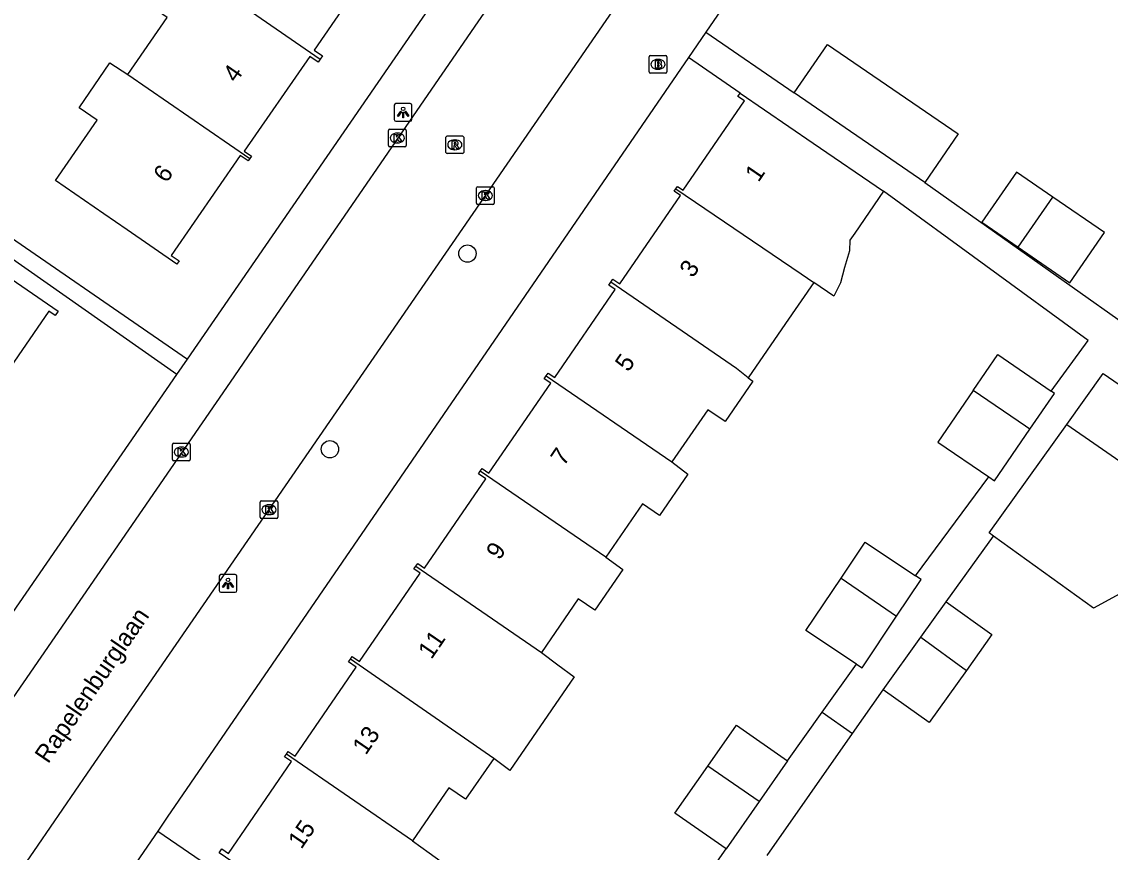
# Model space of a CAD drawing. Extents: x 160158 to 160921, y 381517 to 382041.
# Drawn here: x 160666.6 to 160728, y 381762 to 381808.9 of the extents above; entities that cross this region are included whole.
import ezdxf

# ---------------------------------------------------------------- set-up
doc = ezdxf.new("R2010")
doc.units = 0
for name, color, linetype in [('IMGEO_Boom', 7, 'Continuous'), ('IMGEO_Brandkraan', 7, 'Continuous'), ('IMGEO_Kolk', 7, 'Continuous'), ('IMGEO_Lichtpunt', 7, 'Continuous'), ('IMGEO_Openbare_ruimte_label', 7, 'Continuous'), ('IMGEO_Pand', 7, 'Continuous'), ('IMGEO_Pand_nummerreeks', 7, 'Continuous'), ('IMGEO_Rijbaan_lokaal_open', 7, 'Continuous'), ('IMGEO_Rioolput', 7, 'Continuous'), ('IMGEO_Voetpad_halfverhard', 7, 'Continuous'), ('IMGEO_Voetpad_open', 7, 'Continuous')]:
    doc.layers.add(name, color=color, linetype=linetype)

msp = doc.modelspace()

# ---------------------------------------------------------------- linework, layer by layer
at = {"layer": 'IMGEO_Boom'}
for centre in [(160691.734, 381795.815), (160683.969, 381784.767)]:
    msp.add_circle(centre, 0.489, dxfattribs=at)
at = {"layer": 'IMGEO_Brandkraan'}
for p, q in [((160702.061, 381807.001), (160702.913, 381807.001)), ((160701.986, 381806.075), (160701.986, 381806.927)), ((160702.474, 381806.781), (160702.499, 381806.781)), ((160702.987, 381806.927), (160702.987, 381806.075)), ((160702.913, 381806.001), (160702.061, 381806.001)), ((160702.497, 381806.221), (160702.472, 381806.221))]:
    msp.add_line(p, q, dxfattribs=at)
for points in [[(160702.061, 381807.001), (160702.913, 381807.001)], [(160701.986, 381806.075), (160701.986, 381806.927)], [(160702.334, 381806.701), (160702.334, 381806.301), (160702.547, 381806.301)], [(160702.565, 381806.701), (160702.334, 381806.701)], [(160702.513, 381806.62), (160702.459, 381806.62), (160702.459, 381806.544)], [(160702.459, 381806.544), (160702.512, 381806.544)], [(160702.521, 381806.468), (160702.459, 381806.468), (160702.459, 381806.387)], [(160702.459, 381806.387), (160702.521, 381806.387)], [(160702.987, 381806.927), (160702.987, 381806.075)], [(160702.913, 381806.001), (160702.061, 381806.001)]]:
    msp.add_lwpolyline(points, dxfattribs=at)
for centre, radius, start, end in [((160702.063, 381806.925), 0.0765, 91.55205, 178.44795), ((160702.063, 381806.925), 0.0765, 91.55205, 178.44795), ((160702.911, 381806.925), 0.0765, 1.55205, 88.44795), ((160702.911, 381806.925), 0.0765, 1.55205, 88.44795), ((160702.514, 381806.582), 0.0379, 267.82845, 90.93552), ((160702.522, 381806.427), 0.0404, 269.87594, 90.50774), ((160702.569, 381806.556), 0.145, 59.4692, 91.53667), ((160702.594, 381806.603), 0.0922, 285.51372, 58.15012), ((160702.599, 381806.411), 0.105, 301.31148, 78.98903), ((160702.063, 381806.077), 0.0765, 181.55205, 268.44795), ((160702.063, 381806.077), 0.0765, 181.55205, 268.44795), ((160702.553, 381806.552), 0.251, 268.66757, 293.53466), ((160702.911, 381806.077), 0.0765, 271.55205, 358.44795), ((160702.911, 381806.077), 0.0765, 271.55205, 358.44795)]:
    msp.add_arc(centre, radius, start, end, dxfattribs=at)
for centre, major_axis, ratio, start_param, end_param in [((160702.473, 381806.501), (-0.387, 0.002), 0.722429, 4.712389, 7.853982), ((160702.498, 381806.501), (-0.39, 0.002), 0.717154, 1.570796, 4.712389)]:
    msp.add_ellipse(centre, major_axis=major_axis, ratio=ratio, start_param=start_param, end_param=end_param, dxfattribs=at)
at = {"layer": 'IMGEO_Kolk'}
for p, q in [((160687.276, 381801.916), (160687.276, 381802.768)), ((160687.351, 381802.842), (160688.203, 381802.842)), ((160688.277, 381802.768), (160688.277, 381801.916)), ((160687.787, 381802.062), (160687.762, 381802.062)), ((160687.764, 381802.622), (160687.789, 381802.622)), ((160688.203, 381801.842), (160687.351, 381801.842)), ((160692.321, 381799.592), (160693.173, 381799.592)), ((160692.246, 381798.666), (160692.246, 381799.518)), ((160692.734, 381799.372), (160692.759, 381799.372)), ((160693.247, 381799.518), (160693.247, 381798.666)), ((160693.173, 381798.592), (160692.321, 381798.592)), ((160692.757, 381798.812), (160692.732, 381798.812)), ((160675.087, 381784.181), (160675.087, 381785.033)), ((160675.162, 381785.107), (160676.014, 381785.107)), ((160675.575, 381784.887), (160675.6, 381784.887)), ((160676.088, 381785.033), (160676.088, 381784.181)), ((160675.598, 381784.327), (160675.573, 381784.327)), ((160676.014, 381784.107), (160675.162, 381784.107)), ((160680.036, 381780.925), (160680.036, 381781.777)), ((160680.111, 381781.851), (160680.963, 381781.851)), ((160681.037, 381781.777), (160681.037, 381780.925)), ((160680.524, 381781.631), (160680.549, 381781.631)), ((160680.963, 381780.851), (160680.111, 381780.851)), ((160680.547, 381781.071), (160680.522, 381781.071))]:
    msp.add_line(p, q, dxfattribs=at)
for points in [[(160687.276, 381801.916), (160687.276, 381802.768)], [(160687.351, 381802.842), (160688.203, 381802.842)], [(160688.277, 381802.768), (160688.277, 381801.916)], [(160687.597, 381802.542), (160687.72, 381802.542), (160687.72, 381802.391), (160687.85, 381802.542), (160688.014, 381802.542), (160687.868, 381802.391), (160688.021, 381802.142), (160687.869, 381802.142), (160687.784, 381802.306), (160687.72, 381802.239), (160687.72, 381802.142), (160687.597, 381802.142), (160687.597, 381802.542)], [(160688.203, 381801.842), (160687.351, 381801.842)], [(160692.321, 381799.592), (160693.173, 381799.592)], [(160692.246, 381798.666), (160692.246, 381799.518)], [(160692.567, 381799.292), (160692.69, 381799.292), (160692.69, 381799.141), (160692.82, 381799.292), (160692.984, 381799.292), (160692.838, 381799.141), (160692.991, 381798.892), (160692.839, 381798.892), (160692.754, 381799.056), (160692.69, 381798.989), (160692.69, 381798.892), (160692.567, 381798.892), (160692.567, 381799.292)], [(160693.247, 381799.518), (160693.247, 381798.666)], [(160693.173, 381798.592), (160692.321, 381798.592)], [(160675.087, 381784.181), (160675.087, 381785.033)], [(160675.162, 381785.107), (160676.014, 381785.107)], [(160676.088, 381785.033), (160676.088, 381784.181)], [(160675.408, 381784.807), (160675.531, 381784.807), (160675.531, 381784.656), (160675.661, 381784.807), (160675.825, 381784.807), (160675.679, 381784.656), (160675.832, 381784.407), (160675.68, 381784.407), (160675.595, 381784.571), (160675.531, 381784.504), (160675.531, 381784.407), (160675.408, 381784.407), (160675.408, 381784.807)], [(160676.014, 381784.107), (160675.162, 381784.107)], [(160680.036, 381780.925), (160680.036, 381781.777)], [(160680.111, 381781.851), (160680.963, 381781.851)], [(160681.037, 381781.777), (160681.037, 381780.925)], [(160680.357, 381781.551), (160680.48, 381781.551), (160680.48, 381781.4), (160680.61, 381781.551), (160680.774, 381781.551), (160680.628, 381781.4), (160680.781, 381781.151), (160680.629, 381781.151), (160680.544, 381781.315), (160680.48, 381781.248), (160680.48, 381781.151), (160680.357, 381781.151), (160680.357, 381781.551)], [(160680.963, 381780.851), (160680.111, 381780.851)]]:
    msp.add_lwpolyline(points, dxfattribs=at)
for centre, start, end in [((160687.353, 381802.766), 91.55205, 178.44795), ((160687.353, 381802.766), 91.55205, 178.44795), ((160688.201, 381802.766), 1.55205, 88.44795), ((160688.201, 381802.766), 1.55205, 88.44795), ((160687.353, 381801.918), 181.55205, 268.44795), ((160687.353, 381801.918), 181.55205, 268.44795), ((160688.201, 381801.918), 271.55205, 358.44795), ((160688.201, 381801.918), 271.55205, 358.44795), ((160692.323, 381799.516), 91.55205, 178.44795), ((160692.323, 381799.516), 91.55205, 178.44795), ((160693.171, 381799.516), 1.55205, 88.44795), ((160693.171, 381799.516), 1.55205, 88.44795), ((160692.323, 381798.668), 181.55205, 268.44795), ((160692.323, 381798.668), 181.55205, 268.44795), ((160693.171, 381798.668), 271.55205, 358.44795), ((160693.171, 381798.668), 271.55205, 358.44795), ((160675.164, 381785.031), 91.55205, 178.44795), ((160675.164, 381785.031), 91.55205, 178.44795), ((160676.012, 381785.031), 1.55205, 88.44795), ((160676.012, 381785.031), 1.55205, 88.44795), ((160675.164, 381784.183), 181.55205, 268.44795), ((160675.164, 381784.183), 181.55205, 268.44795), ((160676.012, 381784.183), 271.55205, 358.44795), ((160676.012, 381784.183), 271.55205, 358.44795), ((160680.113, 381781.775), 91.55205, 178.44795), ((160680.113, 381781.775), 91.55205, 178.44795), ((160680.961, 381781.775), 1.55205, 88.44795), ((160680.961, 381781.775), 1.55205, 88.44795), ((160680.113, 381780.927), 181.55205, 268.44795), ((160680.113, 381780.927), 181.55205, 268.44795), ((160680.961, 381780.927), 271.55205, 358.44795), ((160680.961, 381780.927), 271.55205, 358.44795)]:
    msp.add_arc(centre, 0.0765, start, end, dxfattribs=at)
for centre, major_axis, ratio, start_param, end_param in [((160687.763, 381802.342), (-0.387, 0.002), 0.722429, 4.712389, 7.853982), ((160687.788, 381802.342), (-0.39, 0.002), 0.717154, 1.570796, 4.712389), ((160692.733, 381799.092), (-0.387, 0.002), 0.722429, 4.712389, 7.853982), ((160692.758, 381799.092), (-0.39, 0.002), 0.717154, 1.570796, 4.712389), ((160675.574, 381784.607), (-0.387, 0.002), 0.722429, 4.712389, 7.853982), ((160675.599, 381784.607), (-0.39, 0.002), 0.717154, 1.570796, 4.712389), ((160680.523, 381781.351), (-0.387, 0.002), 0.722429, 4.712389, 7.853982), ((160680.548, 381781.351), (-0.39, 0.002), 0.717154, 1.570796, 4.712389)]:
    msp.add_ellipse(centre, major_axis=major_axis, ratio=ratio, start_param=start_param, end_param=end_param, dxfattribs=at)
at = {"layer": 'IMGEO_Lichtpunt'}
for p, q in [((160687.606, 381804.189), (160687.606, 381803.382)), ((160687.606, 381804.189), (160687.606, 381803.382)), ((160688.508, 381804.284), (160687.7, 381804.284)), ((160688.508, 381804.284), (160687.7, 381804.284)), ((160688.602, 381803.382), (160688.602, 381804.189)), ((160688.602, 381803.382), (160688.602, 381804.189)), ((160687.7, 381803.288), (160688.508, 381803.288)), ((160687.7, 381803.288), (160688.508, 381803.288)), ((160677.724, 381777.589), (160677.724, 381776.782)), ((160677.724, 381777.589), (160677.724, 381776.782)), ((160678.626, 381777.684), (160677.818, 381777.684)), ((160678.626, 381777.684), (160677.818, 381777.684)), ((160678.72, 381776.782), (160678.72, 381777.589)), ((160678.72, 381776.782), (160678.72, 381777.589)), ((160677.818, 381776.688), (160678.626, 381776.688)), ((160677.818, 381776.688), (160678.626, 381776.688))]:
    msp.add_line(p, q, dxfattribs=at)
for points in [[(160687.98, 381803.853), (160688.019, 381803.825), (160687.831, 381803.563), (160687.793, 381803.59), (160687.98, 381803.853)], [(160688.082, 381803.805), (160688.129, 381803.805), (160688.129, 381803.483), (160688.082, 381803.483), (160688.082, 381803.805)], [(160688.192, 381803.825), (160688.23, 381803.852), (160688.417, 381803.59), (160688.378, 381803.562), (160688.192, 381803.825)], [(160678.098, 381777.253), (160678.137, 381777.225), (160677.949, 381776.963), (160677.911, 381776.99), (160678.098, 381777.253)], [(160678.2, 381777.205), (160678.247, 381777.205), (160678.247, 381776.883), (160678.2, 381776.883), (160678.2, 381777.205)], [(160678.31, 381777.225), (160678.348, 381777.252), (160678.535, 381776.99), (160678.496, 381776.962), (160678.31, 381777.225)]]:
    msp.add_lwpolyline(points, dxfattribs=at)
for centre in [(160688.105, 381803.987), (160678.223, 381777.387)]:
    msp.add_circle(centre, 0.0994, dxfattribs=at)
for centre, start, end in [((160687.7, 381804.189), 90, 180), ((160687.7, 381804.189), 90, 180), ((160688.508, 381804.189), 0, 90), ((160688.508, 381804.189), 0, 90), ((160687.7, 381803.382), 180, 270), ((160687.7, 381803.382), 180, 270), ((160688.508, 381803.382), 270, 0), ((160688.508, 381803.382), 270, 360), ((160677.818, 381777.589), 90, 180), ((160677.818, 381777.589), 90, 180), ((160678.626, 381777.589), 0, 90), ((160678.626, 381777.589), 0, 90), ((160677.818, 381776.782), 180, 270), ((160677.818, 381776.782), 180, 270), ((160678.626, 381776.782), 270, 0), ((160678.626, 381776.782), 270, 360)]:
    msp.add_arc(centre, 0.0946, start, end, dxfattribs=at)
at = {"layer": 'IMGEO_Pand'}
for points in [[(160674.793, 381812.761), (160677.226, 381816.289), (160677.621, 381816.017), (160680.448, 381820.118), (160680.755, 381819.906), (160683.504, 381818.011), (160682.279, 381816.233), (160683.308, 381815.523), (160687.425, 381812.686), (160687.229, 381812.402), (160686.795, 381812.701), (160683.076, 381807.306), (160683.552, 381806.978), (160683.43, 381806.8)], [(160672.564, 381805.927), (160674.782, 381809.143), (160673.803, 381809.818), (160673.072, 381810.264), (160674.793, 381812.761)], [(160674.793, 381812.761), (160675.497, 381812.275), (160676.513, 381811.574), (160683.43, 381806.8)], [(160710.181, 381804.887), (160712.056, 381807.621), (160719.424, 381802.569), (160717.549, 381799.835)], [(160679.442, 381801.183), (160679.348, 381801.047), (160678.901, 381801.355), (160675.013, 381795.714), (160675.459, 381795.407), (160675.328, 381795.216), (160672.528, 381797.146), (160671.212, 381798.054), (160668.478, 381799.938), (160670.827, 381803.346), (160669.811, 381804.046), (160671.556, 381806.578), (160672.564, 381805.927)], [(160683.43, 381806.8), (160683.307, 381806.621), (160682.831, 381806.949), (160679.14, 381801.595), (160679.537, 381801.322), (160679.442, 381801.183)], [(160672.564, 381805.927), (160679.442, 381801.183)], [(160703.497, 381799.471), (160703.593, 381799.61), (160703.901, 381799.399), (160707.362, 381804.446), (160706.999, 381804.694), (160707.123, 381804.875)], [(160707.123, 381804.875), (160711.247, 381802.048), (160715.209, 381799.331)], [(160717.549, 381799.835), (160710.181, 381804.887)], [(160724.771, 381799.007), (160722.724, 381800.419), (160720.771, 381797.589), (160722.818, 381796.176)], [(160699.825, 381794.197), (160699.941, 381794.365), (160700.326, 381794.1), (160703.749, 381799.091), (160703.401, 381799.33), (160703.497, 381799.471)], [(160703.497, 381799.471), (160710.569, 381794.667), (160711.277, 381794.186)], [(160715.209, 381799.331), (160713.593, 381796.974), (160713.313, 381796.566), (160713.304, 381795.975), (160713.016, 381795.03), (160712.784, 381794.163), (160712.408, 381793.418), (160711.277, 381794.186)], [(160722.818, 381796.176), (160724.771, 381799.007)], [(160722.818, 381796.176), (160725.728, 381794.168), (160727.681, 381796.998), (160724.771, 381799.007)], [(160657.351, 381792.288), (160657.127, 381794.303), (160657.645, 381795.057), (160659.263, 381795.483), (160660.906, 381797.872), (160664.512, 381795.392), (160668.631, 381792.558), (160668.466, 381792.319), (160668.101, 381792.57), (160664.628, 381787.522), (160665.013, 381787.257), (160664.888, 381787.076)], [(160696.176, 381788.907), (160696.285, 381789.067), (160696.659, 381788.81), (160700.068, 381793.782), (160699.709, 381794.028), (160699.825, 381794.197)], [(160707.585, 381788.801), (160706.923, 381789.329), (160699.825, 381794.197)], [(160711.277, 381794.186), (160709.681, 381791.859), (160707.585, 381788.801)], [(160720.269, 381788.078), (160721.661, 381790.109), (160724.68, 381788.039)], [(160692.453, 381783.534), (160692.555, 381783.683), (160692.947, 381783.415), (160696.433, 381788.498), (160696.067, 381788.749), (160696.176, 381788.907)], [(160696.176, 381788.907), (160703.265, 381784.045)], [(160707.585, 381788.801), (160707.831, 381788.604), (160706.271, 381786.328), (160705.291, 381786.999), (160703.265, 381784.045)], [(160720.269, 381788.078), (160718.278, 381785.174), (160721.15, 381783.205)], [(160723.476, 381785.899), (160723.237, 381786.062), (160720.269, 381788.078)], [(160723.476, 381785.899), (160724.859, 381787.916), (160724.68, 381788.039)], [(160721.421, 381779.855), (160721.169, 381780.037), (160725.558, 381786.168)], [(160725.558, 381786.168), (160731.355, 381782.148), (160728.591, 381778.227), (160729.581, 381777.174), (160727.057, 381775.795), (160721.421, 381779.855)], [(160721.15, 381783.205), (160721.476, 381782.981), (160723.476, 381785.899)], [(160703.265, 381784.045), (160704.175, 381783.352), (160702.578, 381781.024), (160701.618, 381781.683), (160699.549, 381778.667)], [(160688.819, 381778.159), (160688.925, 381778.312), (160689.306, 381778.051), (160692.767, 381783.099), (160692.351, 381783.385), (160692.453, 381783.534)], [(160699.549, 381778.667), (160692.453, 381783.534)], [(160712.817, 381777.494), (160714.173, 381779.521), (160717.018, 381777.619)], [(160685.131, 381772.905), (160685.235, 381773.057), (160685.647, 381772.775), (160689.068, 381777.765), (160688.715, 381778.007), (160688.819, 381778.159)], [(160688.819, 381778.159), (160695.912, 381773.294)], [(160699.549, 381778.667), (160700.499, 381777.973), (160698.926, 381775.679), (160697.988, 381776.322), (160695.912, 381773.294)], [(160713.682, 381772.634), (160710.839, 381774.536), (160712.817, 381777.494)], [(160712.817, 381777.494), (160715.651, 381775.55), (160715.956, 381775.341)], [(160715.956, 381775.341), (160717.337, 381777.405), (160717.018, 381777.619)], [(160717.328, 381774.155), (160718.748, 381776.145)], [(160718.748, 381776.145), (160721.334, 381774.3), (160719.892, 381772.28)], [(160713.682, 381772.634), (160714.003, 381772.42), (160715.956, 381775.341)], [(160715.204, 381771.179), (160717.328, 381774.155)], [(160717.328, 381774.155), (160719.892, 381772.28)], [(160695.912, 381773.294), (160696.84, 381772.6), (160697.757, 381771.914), (160694.13, 381766.627), (160693.214, 381767.308)], [(160681.518, 381767.542), (160681.622, 381767.694), (160682.003, 381767.432), (160685.454, 381772.465), (160685.029, 381772.756), (160685.131, 381772.905)], [(160693.214, 381767.308), (160685.131, 381772.905)], [(160719.892, 381772.28), (160717.79, 381769.334), (160715.204, 381771.179)], [(160705.291, 381766.861), (160706.912, 381769.187), (160709.796, 381767.178)], [(160688.635, 381762.661), (160689.564, 381761.979), (160690.583, 381761.231), (160686.816, 381755.737), (160684.779, 381757.134), (160683.917, 381757.725), (160681.842, 381759.148), (160677.718, 381761.975), (160677.871, 381762.199), (160678.246, 381761.942), (160681.799, 381767.123), (160681.413, 381767.388), (160681.518, 381767.542)], [(160688.635, 381762.661), (160681.518, 381767.542)], [(160693.214, 381767.308), (160691.629, 381764.996), (160690.682, 381765.646), (160688.635, 381762.661)], [(160709.796, 381767.178), (160708.19, 381764.872)], [(160706.329, 381762.2), (160703.444, 381764.21), (160705.291, 381766.861)], [(160708.19, 381764.872), (160705.291, 381766.861)], [(160708.19, 381764.872), (160706.329, 381762.2)]]:
    msp.add_lwpolyline(points, dxfattribs=at)
at = {"layer": 'IMGEO_Rijbaan_lokaal_open'}
for points in [[(160711.248, 381836.325), (160711.08, 381836.076), (160707.501, 381830.956), (160699.651, 381819.545), (160692.328, 381808.901), (160680.332, 381791.464), (160678.334, 381788.56), (160651.806, 381750), (160643.136, 381737.367), (160641.13, 381734.448), (160614.441, 381695.549), (160610.996, 381690.462), (160609.452, 381688.229)], [(160614.454, 381684.835), (160615.999, 381687.121), (160619.05, 381691.582), (160640.187, 381722.521), (160642.496, 381725.9), (160658.96, 381750), (160667.503, 381762.414), (160670.296, 381766.471), (160700.524, 381810.394), (160703.573, 381814.824), (160712.504, 381827.801), (160716.028, 381832.837), (160716.089, 381833.009)]]:
    msp.add_lwpolyline(points, dxfattribs=at)
at = {"layer": 'IMGEO_Rioolput'}
for p, q in [((160690.519, 381801.531), (160690.519, 381802.383)), ((160690.594, 381802.457), (160691.446, 381802.457)), ((160691.007, 381802.237), (160691.032, 381802.237)), ((160691.52, 381802.383), (160691.52, 381801.531)), ((160691.446, 381801.457), (160690.594, 381801.457)), ((160691.03, 381801.677), (160691.005, 381801.677))]:
    msp.add_line(p, q, dxfattribs=at)
for points in [[(160690.519, 381801.531), (160690.519, 381802.383)], [(160690.594, 381802.457), (160691.446, 381802.457)], [(160691.108, 381802.155), (160690.856, 381802.157), (160690.856, 381801.757)], [(160691.034, 381802.076), (160690.98, 381802.076), (160690.98, 381801.995)], [(160691.52, 381802.383), (160691.52, 381801.531)], [(160691.446, 381801.457), (160690.594, 381801.457)], [(160690.856, 381801.757), (160690.98, 381801.757), (160690.98, 381801.919), (160690.991, 381801.919)], [(160690.98, 381801.995), (160691.032, 381801.995)], [(160691.038, 381801.89), (160691.109, 381801.757), (160691.249, 381801.757), (160691.184, 381801.883)]]:
    msp.add_lwpolyline(points, dxfattribs=at)
for centre, radius, start, end in [((160690.596, 381802.381), 0.0765, 91.55205, 178.44795), ((160690.596, 381802.381), 0.0765, 91.55205, 178.44795), ((160691.04, 381801.98), 0.0964, 77.00612, 93.18647), ((160691.054, 381802.037), 0.0378, 276.66336, 79.67722), ((160691.107, 381802.045), 0.109, 350.36119, 89.41601), ((160691.444, 381802.381), 0.0765, 1.55205, 88.44795), ((160691.444, 381802.381), 0.0765, 1.55205, 88.44795), ((160690.596, 381801.533), 0.0765, 181.55205, 268.44795), ((160690.596, 381801.533), 0.0765, 181.55205, 268.44795), ((160690.99, 381801.866), 0.0533, 26.02933, 88.69889), ((160691.016, 381802.184), 0.19, 274.7715, 282.96867), ((160691.105, 381802.045), 0.112, 277.58423, 350.98172), ((160691.089, 381801.83), 0.108, 29.51342, 73.79051), ((160691.444, 381801.533), 0.0765, 271.55205, 358.44795), ((160691.444, 381801.533), 0.0765, 271.55205, 358.44795)]:
    msp.add_arc(centre, radius, start, end, dxfattribs=at)
for centre, major_axis, ratio, start_param, end_param in [((160691.006, 381801.957), (-0.387, 0.002), 0.722429, 4.712389, 7.853982), ((160691.031, 381801.957), (-0.39, 0.002), 0.717154, 1.570796, 4.712389)]:
    msp.add_ellipse(centre, major_axis=major_axis, ratio=ratio, start_param=start_param, end_param=end_param, dxfattribs=at)
at = {"layer": 'IMGEO_Voetpad_halfverhard'}
for points in [[(160705.185, 381808.313), (160710.181, 381804.887)], [(160707.123, 381804.875), (160704.201, 381806.878)], [(160717.549, 381799.835), (160729.351, 381791.476), (160728.862, 381790.786), (160731.12, 381788.973), (160731.34, 381788.817)], [(160724.68, 381788.039), (160726.766, 381790.897), (160715.209, 381799.331)], [(160725.558, 381786.168), (160727.618, 381789.046), (160735.153, 381783.849), (160753.822, 381770.972)], [(160717.018, 381777.619), (160721.15, 381783.205)], [(160718.748, 381776.145), (160721.421, 381779.855)], [(160711.747, 381769.917), (160713.682, 381772.634)], [(160713.472, 381768.708), (160715.204, 381771.179)]]:
    msp.add_lwpolyline(points, dxfattribs=at)
at = {"layer": 'IMGEO_Voetpad_open'}
for points in [[(160719.08, 381828.577), (160705.185, 381808.313)], [(160659.823, 381819.644), (160660.862, 381818.835), (160653.268, 381809.14), (160651.567, 381806.643), (160675.928, 381789.86)], [(160675.928, 381789.86), (160692.079, 381813.304)], [(160705.185, 381808.313), (160704.201, 381806.878)], [(160704.201, 381806.878), (160674.789, 381763.984), (160674.255, 381763.205)], [(160675.328, 381788.989), (160654.242, 381803.777)], [(160675.328, 381788.989), (160675.928, 381789.86)], [(160641.671, 381740.128), (160648.467, 381750), (160675.328, 381788.989)], [(160709.796, 381767.178), (160711.747, 381769.917)], [(160711.747, 381769.917), (160713.472, 381768.708)], [(160708.643, 381761.815), (160713.472, 381768.708)], [(160674.255, 381763.205), (160673.051, 381761.449)], [(160674.255, 381763.205), (160683.384, 381756.947), (160693.336, 381750.054), (160694.595, 381749.193)], [(160702.195, 381756.292), (160706.329, 381762.2)]]:
    msp.add_lwpolyline(points, dxfattribs=at)

# ---------------------------------------------------------------- texts
at = {"layer": 'IMGEO_Openbare_ruimte_label'}
msp.add_text('Rapelenburglaan', height=1, rotation=55.59477, dxfattribs=at).set_placement((160668.067, 381766.964))
at = {"layer": 'IMGEO_Pand_nummerreeks'}
for s, rotation, p in [('4', 55.25605, (160678.677, 381805.417)), ('6', 55.25524, (160674.75, 381799.755)), ('1', 55.58837, (160708.157, 381799.802)), ('3', 55.58837, (160704.453, 381794.395)), ('5', 55.58837, (160700.814, 381789.082)), ('7', 55.58816, (160697.174, 381783.77)), ('9', 55.58816, (160693.535, 381778.457)), ('11', 55.58816, (160689.699, 381772.859)), ('13', 55.58816, (160685.996, 381767.452)), ('15', 55.58837, (160682.357, 381762.139))]:
    msp.add_text(s, height=1, rotation=rotation, dxfattribs=at).set_placement(p)

doc.saveas('drawing.dxf')
